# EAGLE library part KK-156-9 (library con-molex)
KK 156 HEADER Source: http://www.molex.com/pdm_docs/sd/026604100_sd.pdf
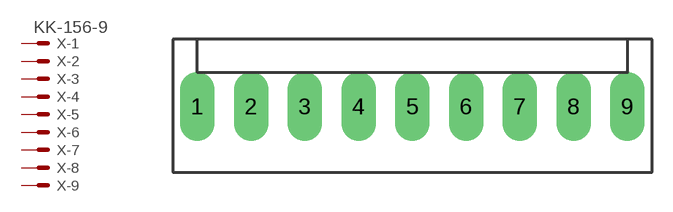
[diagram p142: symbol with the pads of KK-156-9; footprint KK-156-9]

Designator prefix X; gates -1=MV -2=M -3=M -4=M -5=M -6=M -7=M -8=M -9=M

## KK-156-9 (OC_FARNELL: unknown; OC_NEWARK: unknown)  [KK-156-9]
1  -1:S  pas
2  -2:S  pas
3  -3:S  pas
4  -4:S  pas
5  -5:S  pas
6  -6:S  pas
7  -7:S  pas
8  -8:S  pas
9  -9:S  pas

## Footprint KK-156-9 (pad centres in mm)
KK 156 HEADER Source: http://www.molex.com/pdm_docs/sd/026604100_sd.pdf
drill 1.7 pad 2.184 long: 1 -15.84,0; 2 -11.88,0; 3 -7.92,0; 4 -3.96,0; 5 0,0; 6 3.96,0; 7 7.92,0; 8 11.88,0; 9 15.84,0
